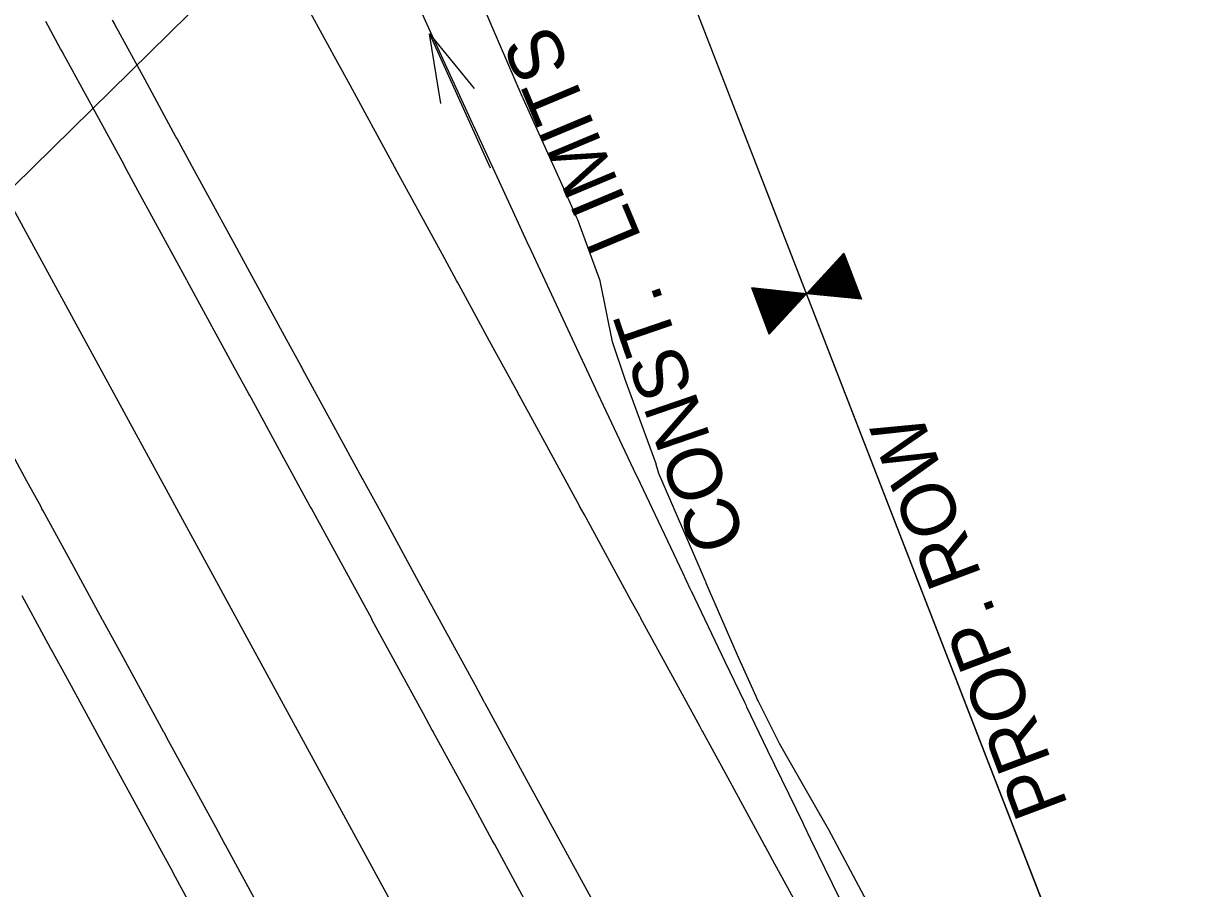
# Model space of a CAD drawing. Extents: x 1627557 to 1636561, y 783843 to 794002.
# Drawn here: x 1628086.3 to 1628204.6, y 784798.1 to 784885.9 of the extents above; entities that cross this region are included whole.
import ezdxf

# ---------------------------------------------------------------- set-up
doc = ezdxf.new("R2010")
doc.units = 0
for name, color, linetype in [('25 FT Buffer', 7, 'Continuous'), ('Flow Arrows', 7, 'Continuous'), ('GATE', 7, 'Continuous'), ('R_Clearzone', 7, 'Continuous'), ('R_Ditch', 7, 'Continuous'), ('R_Horz Alg', 7, 'Continuous'), ('R_Proposed Const Limits', 7, 'Continuous'), ('R_Proposed Const Limits Annot', 7, 'Continuous'), ('R_Proposed Road', 7, 'Continuous'), ('R_Proposed Shoulder', 7, 'Continuous'), ('R_ROW', 7, 'Continuous'), ('R_ROW Annot Labels', 7, 'Continuous')]:
    doc.layers.add(name, color=color, linetype=linetype)

msp = doc.modelspace()

# ---------------------------------------------------------------- linework, layer by layer
at = {"layer": '25 FT Buffer'}
for points in [[(1628198.17, 784774.92), (1628099.65, 785028.73), (1628058.95, 785040.71)], [(1628128.73, 784912.02), (1628047.84, 784832.47), (1628028.94, 784828.64), (1627988.66, 784820.54), (1627954.84, 784809.03), (1627927.06, 784808.64), (1627894.29, 784799.05), (1627847.27, 784784.48), (1627792.52, 784755.67), (1627716.91, 784734.64)]]:
    msp.add_lwpolyline(points, dxfattribs=at)
at = {"layer": 'Flow Arrows'}
msp.add_line((1628127.51, 784884.8), (1628133.66, 784871.2), dxfattribs=at)
msp.add_lwpolyline([(1628128.66, 784877.73), (1628127.51, 784884.8), (1628132.06, 784879.26)], dxfattribs=at)
at = {"layer": 'GATE'}
for p, q in [((1628170.79, 784857.91), (1628169.2, 784862.15)), ((1628170.9, 784857.9), (1628169.27, 784862.23)), ((1628171.01, 784857.89), (1628169.35, 784862.31)), ((1628171.13, 784857.88), (1628169.42, 784862.39)), ((1628171.24, 784857.86), (1628169.5, 784862.48)), ((1628169.23, 784858.07), (1628168.13, 784861)), ((1628169.35, 784858.06), (1628168.21, 784861.08)), ((1628169.46, 784858.05), (1628168.28, 784861.16)), ((1628169.57, 784858.04), (1628168.36, 784861.25)), ((1628169.68, 784858.03), (1628168.44, 784861.33)), ((1628169.79, 784858.01), (1628168.51, 784861.41)), ((1628169.9, 784858), (1628168.59, 784861.49)), ((1628170.01, 784857.99), (1628168.66, 784861.57)), ((1628170.12, 784857.98), (1628168.74, 784861.66)), ((1628170.24, 784857.97), (1628168.82, 784861.74)), ((1628170.35, 784857.96), (1628168.89, 784861.82)), ((1628170.46, 784857.95), (1628168.97, 784861.9)), ((1628170.57, 784857.93), (1628169.04, 784861.98)), ((1628170.68, 784857.92), (1628169.12, 784862.07)), ((1628167.57, 784858.25), (1628166.99, 784859.77)), ((1628167.68, 784858.23), (1628167.07, 784859.85)), ((1628167.79, 784858.22), (1628167.14, 784859.93)), ((1628167.9, 784858.21), (1628167.22, 784860.02)), ((1628168.01, 784858.2), (1628167.3, 784860.1)), ((1628168.12, 784858.19), (1628167.37, 784860.18)), ((1628168.23, 784858.18), (1628167.45, 784860.26)), ((1628168.35, 784858.16), (1628167.52, 784860.34)), ((1628168.46, 784858.15), (1628167.6, 784860.43)), ((1628168.57, 784858.14), (1628167.68, 784860.51)), ((1628168.68, 784858.13), (1628167.75, 784860.59)), ((1628168.79, 784858.12), (1628167.83, 784860.67)), ((1628168.9, 784858.11), (1628167.9, 784860.75)), ((1628169.01, 784858.1), (1628167.98, 784860.84)), ((1628169.12, 784858.08), (1628168.06, 784860.92)), ((1628161.97, 784854.34), (1628160.21, 784859.01)), ((1628162.04, 784854.43), (1628160.32, 784859)), ((1628162.12, 784854.51), (1628160.43, 784858.99)), ((1628162.2, 784854.59), (1628160.54, 784858.98)), ((1628162.27, 784854.67), (1628160.66, 784858.96)), ((1628162.35, 784854.75), (1628160.77, 784858.95)), ((1628162.42, 784854.84), (1628160.88, 784858.94)), ((1628162.5, 784854.92), (1628160.99, 784858.93)), ((1628162.58, 784855), (1628161.1, 784858.92)), ((1628162.65, 784855.08), (1628161.21, 784858.91)), ((1628162.73, 784855.16), (1628161.32, 784858.89)), ((1628162.8, 784855.25), (1628161.43, 784858.88)), ((1628162.88, 784855.33), (1628161.55, 784858.87)), ((1628162.96, 784855.41), (1628161.66, 784858.86)), ((1628163.03, 784855.49), (1628161.77, 784858.85)), ((1628163.11, 784855.57), (1628161.88, 784858.84)), ((1628163.18, 784855.66), (1628161.99, 784858.83)), ((1628163.26, 784855.74), (1628162.1, 784858.81)), ((1628163.34, 784855.82), (1628162.21, 784858.8)), ((1628163.41, 784855.9), (1628162.32, 784858.79)), ((1628163.49, 784855.98), (1628162.44, 784858.78)), ((1628163.56, 784856.07), (1628162.55, 784858.77)), ((1628163.64, 784856.15), (1628162.66, 784858.76)), ((1628163.72, 784856.23), (1628162.77, 784858.74)), ((1628163.79, 784856.31), (1628162.88, 784858.73)), ((1628163.87, 784856.39), (1628162.99, 784858.72)), ((1628163.94, 784856.48), (1628163.1, 784858.71)), ((1628164.02, 784856.56), (1628163.21, 784858.7)), ((1628164.1, 784856.64), (1628163.32, 784858.69)), ((1628164.17, 784856.72), (1628163.44, 784858.67)), ((1628164.25, 784856.8), (1628163.55, 784858.66)), ((1628164.32, 784856.89), (1628163.66, 784858.65)), ((1628164.4, 784856.97), (1628163.77, 784858.64)), ((1628164.48, 784857.05), (1628163.88, 784858.63)), ((1628164.55, 784857.13), (1628163.99, 784858.62)), ((1628164.63, 784857.21), (1628164.1, 784858.61)), ((1628164.7, 784857.3), (1628164.21, 784858.59)), ((1628164.78, 784857.38), (1628164.33, 784858.58)), ((1628166.01, 784858.41), (1628165.93, 784858.62)), ((1628166.12, 784858.4), (1628166.01, 784858.7)), ((1628166.23, 784858.38), (1628166.08, 784858.79)), ((1628166.34, 784858.37), (1628166.16, 784858.87)), ((1628166.45, 784858.36), (1628166.23, 784858.95)), ((1628166.57, 784858.35), (1628166.31, 784859.03)), ((1628166.68, 784858.34), (1628166.39, 784859.11)), ((1628166.79, 784858.33), (1628166.46, 784859.2)), ((1628166.9, 784858.32), (1628166.54, 784859.28)), ((1628167.01, 784858.3), (1628166.61, 784859.36)), ((1628167.12, 784858.29), (1628166.69, 784859.44)), ((1628167.23, 784858.28), (1628166.77, 784859.52)), ((1628167.34, 784858.27), (1628166.84, 784859.61)), ((1628167.46, 784858.26), (1628166.92, 784859.69)), ((1628164.85, 784857.46), (1628164.44, 784858.57)), ((1628164.93, 784857.54), (1628164.55, 784858.56)), ((1628165.01, 784857.63), (1628164.66, 784858.55)), ((1628165.08, 784857.71), (1628164.77, 784858.54)), ((1628165.16, 784857.79), (1628164.88, 784858.52)), ((1628165.23, 784857.87), (1628164.99, 784858.51)), ((1628165.31, 784857.95), (1628165.1, 784858.5)), ((1628165.39, 784858.04), (1628165.22, 784858.49)), ((1628165.46, 784858.12), (1628165.33, 784858.48)), ((1628165.54, 784858.2), (1628165.44, 784858.47)), ((1628165.61, 784858.28), (1628165.55, 784858.46)), ((1628165.69, 784858.36), (1628165.66, 784858.44)), ((1628165.79, 784858.43), (1628165.78, 784858.46)), ((1628165.9, 784858.42), (1628165.85, 784858.54))]:
    msp.add_line(p, q, dxfattribs=at)
for points in [[(1628171.32, 784857.86), (1628165.76, 784858.43), (1628169.55, 784862.54)], [(1628161.96, 784854.33), (1628165.76, 784858.43), (1628160.2, 784859.01)]]:
    msp.add_lwpolyline(points, close=True, dxfattribs=at)
at = {"layer": 'R_Clearzone'}
msp.add_lwpolyline([(1628167.13, 784792.16), (1628162.34, 784800.94), (1628161.56, 784802.38), (1628161.55, 784802.39), (1628161.47, 784802.55), (1628157.56, 784809.72), (1628155.21, 784814.03), (1628155.14, 784814.15), (1628154.96, 784814.48), (1628152.77, 784818.5), (1628148.97, 784825.46), (1628148.95, 784825.51), (1628148.85, 784825.7), (1628147.98, 784827.28), (1628143.2, 784836.06), (1628142.75, 784836.87), (1628142.74, 784836.9), (1628142.73, 784836.92), (1628138.41, 784844.84), (1628136.61, 784848.14), (1628136.56, 784848.23), (1628136.51, 784848.33), (1628133.62, 784853.62), (1628130.49, 784859.36), (1628130.37, 784859.59), (1628130.27, 784859.77), (1628128.83, 784862.4), (1628124.05, 784871.17), (1628124.05, 784871.18), (1628124.03, 784871.21), (1628123.98, 784871.3), (1628119.26, 784879.96), (1628117.7, 784882.83), (1628117.7, 784882.83), (1628117.62, 784882.98), (1628114.47, 784888.74)], dxfattribs=at)
at = {"layer": 'R_Ditch'}
msp.add_lwpolyline([(1628170.59, 784794.05), (1628166.2, 784803.05), (1628165.49, 784804.53), (1628165.48, 784804.54), (1628165.41, 784804.7), (1628161.85, 784812.06), (1628159.72, 784816.49), (1628159.66, 784816.61), (1628159.49, 784816.95), (1628157.51, 784821.09), (1628154.09, 784828.25), (1628154.06, 784828.3), (1628153.97, 784828.49), (1628153.2, 784830.12), (1628148.91, 784839.17), (1628148.51, 784840.01), (1628148.5, 784840.04), (1628148.49, 784840.06), (1628144.64, 784848.24), (1628143.04, 784851.65), (1628142.99, 784851.74), (1628142.95, 784851.84), (1628140.39, 784857.31), (1628137.63, 784863.25), (1628137.51, 784863.49), (1628137.43, 784863.67), (1628136.17, 784866.4), (1628131.97, 784875.49), (1628131.97, 784875.5), (1628131.95, 784875.53), (1628131.91, 784875.62), (1628127.79, 784884.61), (1628126.43, 784887.59)], dxfattribs=at)
at = {"layer": 'R_Horz Alg'}
msp.add_line((1628236.53, 784589.68), (1627810.31, 785371.39), dxfattribs=at)
at = {"layer": 'R_Proposed Const Limits'}
msp.add_lwpolyline([(1628172.73, 784795.22), (1628168.03, 784804.04), (1628167.21, 784805.46), (1628167.21, 784805.47), (1628167.12, 784805.63), (1628163.05, 784812.72), (1628160.85, 784817.11), (1628160.79, 784817.23), (1628160.64, 784817.57), (1628158.76, 784821.77), (1628155.59, 784829.07), (1628155.57, 784829.12), (1628155.49, 784829.32), (1628154.76, 784830.98), (1628150.79, 784840.2), (1628150.52, 784841.11), (1628150.51, 784841.14), (1628150.5, 784841.16), (1628147.36, 784849.72), (1628146.14, 784853.34), (1628146.12, 784853.45), (1628146.09, 784853.56), (1628144.84, 784859.74), (1628142.55, 784865.94), (1628142.44, 784866.18), (1628142.36, 784866.36), (1628141.13, 784869.1), (1628137.03, 784878.24), (1628137.02, 784878.25), (1628137.01, 784878.29), (1628136.97, 784878.37), (1628133.04, 784887.47)], dxfattribs=at)
at = {"layer": 'R_Proposed Road'}
for points in [[(1628140.4, 784791.06), (1628136.49, 784798.23), (1628134.14, 784802.54), (1628134.07, 784802.66), (1628133.89, 784802.99), (1628131.7, 784807.01), (1628127.9, 784813.98), (1628127.88, 784814.02), (1628127.77, 784814.21), (1628126.91, 784815.79), (1628122.12, 784824.57), (1628121.68, 784825.38), (1628121.67, 784825.41), (1628121.66, 784825.43), (1628117.34, 784833.35), (1628115.54, 784836.65), (1628115.49, 784836.74), (1628115.43, 784836.84), (1628112.55, 784842.13), (1628109.42, 784847.87), (1628109.29, 784848.1), (1628109.2, 784848.28), (1628107.76, 784850.91), (1628102.98, 784859.68), (1628102.98, 784859.69), (1628102.96, 784859.72), (1628102.91, 784859.81), (1628098.19, 784868.47), (1628096.63, 784871.34), (1628096.63, 784871.34), (1628096.54, 784871.49), (1628093.4, 784877.25), (1628090.34, 784882.87), (1628090.29, 784882.96), (1628090.11, 784883.29), (1628088.62, 784886.03)], [(1628110.63, 784795.52), (1628106.83, 784802.49), (1628106.8, 784802.54), (1628106.7, 784802.72), (1628105.84, 784804.3), (1628101.05, 784813.08), (1628100.61, 784813.9), (1628100.6, 784813.92), (1628100.58, 784813.94), (1628096.27, 784821.86), (1628094.47, 784825.16), (1628094.42, 784825.26), (1628094.36, 784825.35), (1628091.48, 784830.64), (1628088.35, 784836.39), (1628088.22, 784836.62), (1628088.13, 784836.79), (1628086.69, 784839.42), (1628081.91, 784848.19)]]:
    msp.add_lwpolyline(points, dxfattribs=at)
at = {"layer": 'R_Proposed Shoulder'}
for points in [[(1628145.66, 784793.93), (1628141.75, 784801.11), (1628139.4, 784805.41), (1628139.34, 784805.54), (1628139.16, 784805.86), (1628136.97, 784809.89), (1628133.17, 784816.85), (1628133.14, 784816.9), (1628133.04, 784817.08), (1628132.18, 784818.67), (1628127.39, 784827.45), (1628126.95, 784828.26), (1628126.94, 784828.28), (1628126.92, 784828.3), (1628122.61, 784836.22), (1628120.81, 784839.53), (1628120.76, 784839.62), (1628120.7, 784839.72), (1628117.82, 784845), (1628114.69, 784850.75), (1628114.56, 784850.98), (1628114.47, 784851.15), (1628113.03, 784853.78), (1628108.25, 784862.55), (1628108.24, 784862.56), (1628108.23, 784862.59), (1628108.18, 784862.68), (1628103.46, 784871.34), (1628101.89, 784874.21), (1628101.89, 784874.21), (1628101.81, 784874.36), (1628098.67, 784880.12), (1628095.61, 784885.74), (1628095.56, 784885.83), (1628095.37, 784886.17)], [(1628105.36, 784792.65), (1628101.56, 784799.61), (1628101.54, 784799.66), (1628101.44, 784799.85), (1628100.57, 784801.43), (1628095.79, 784810.21), (1628095.34, 784811.02), (1628095.33, 784811.05), (1628095.32, 784811.07), (1628091, 784818.99), (1628089.2, 784822.29), (1628089.15, 784822.38), (1628089.1, 784822.48), (1628086.21, 784827.77)]]:
    msp.add_lwpolyline(points, dxfattribs=at)
at = {"layer": 'R_ROW'}
msp.add_line((1628198.17, 784774.92), (1628099.65, 785028.73), dxfattribs=at)

# ---------------------------------------------------------------- texts
at = {"layer": 'R_Proposed Const Limits Annot'}
for s, rotation, p in [(' LIMITS', 112.7325, (1628149.88, 784862.18)), ('CONST. ', 108.9154, (1628159.66, 784833.32))]:
    msp.add_text(s, height=5.5, rotation=rotation, dxfattribs=at).set_placement(p)
at = {"layer": 'R_ROW Annot Labels'}
msp.add_text('PROP. ROW', height=5.5, rotation=110.5928, dxfattribs=at).set_placement((1628192.34, 784806.51))

doc.saveas('drawing.dxf')
